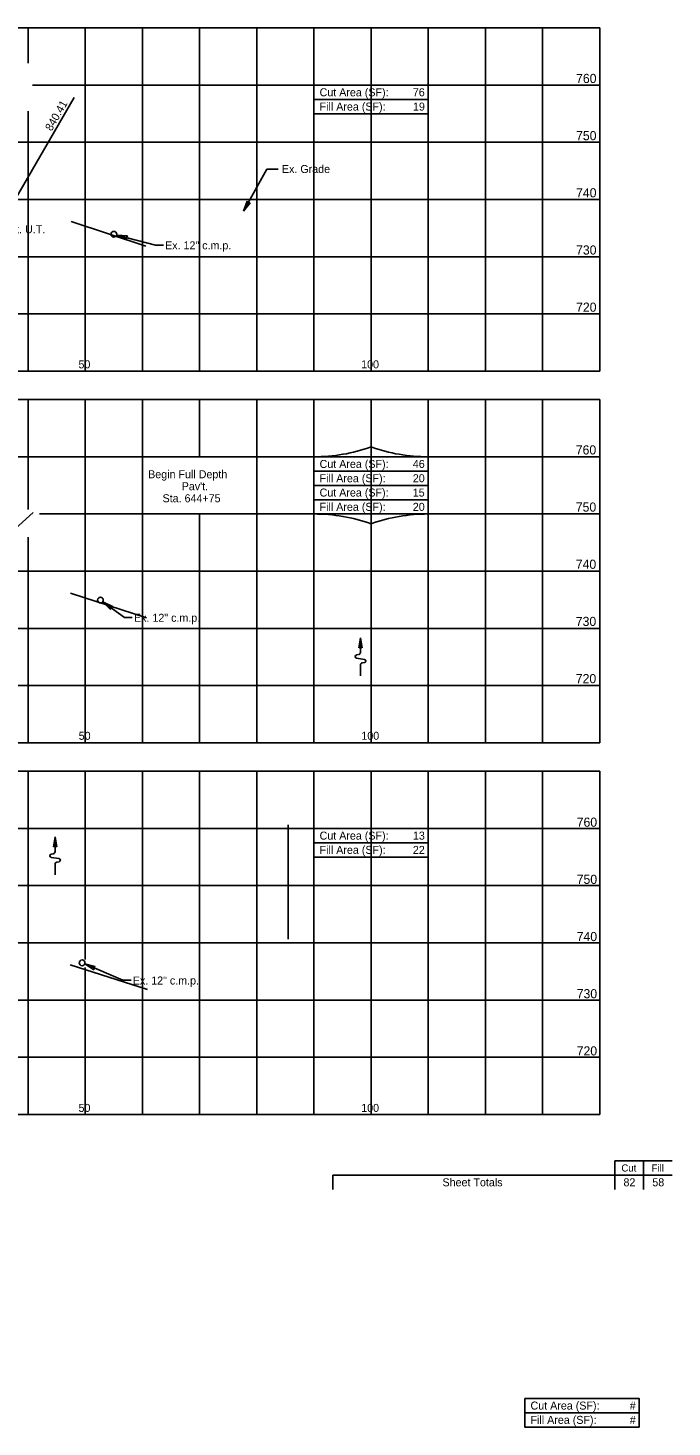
# Model space of a CAD drawing. Extents: x -475 to 76, y 0 to 417.
# Drawn here: x -455.81 to -444.54, y 392.1 to 416.57 of the extents above; entities that cross this region are included whole.
import ezdxf

# ---------------------------------------------------------------- set-up
doc = ezdxf.new("R2010")
doc.units = 0
for name, color, linetype in [('Default', 7, 'Continuous'), ('DR_X_Culvert', 7, 'Continuous'), ('DR_X_Storm_Sewer', 7, 'Continuous'), ('RW_X_Esmt_SH', 7, 'Continuous'), ('SC_Scratch1', 7, 'Continuous'), ('SC_Scratch10', 7, 'Continuous'), ('SH_Masking', 7, 'Continuous'), ('SV_P_Mon_Cells_Set', 7, 'Continuous')]:
    doc.layers.add(name, color=color, linetype=linetype)

msp = doc.modelspace()

# ---------------------------------------------------------------- linework, layer by layer
at = {"layer": 'Default'}
for p, q in [((-451.632, 414.099), (-452.039, 413.361)), ((-451.432, 414.099), (-451.632, 414.099)), ((-452.039, 413.361), (-451.977, 413.538)), ((-451.923, 413.508), (-452.039, 413.361)), ((-451.977, 413.538), (-451.977, 413.538)), ((-451.923, 413.508), (-451.923, 413.508)), ((-454.071, 412.929), (-454.257, 412.946)), ((-454.257, 412.946), (-454.086, 412.869)), ((-454.257, 412.946), (-453.577, 412.771)), ((-454.086, 412.869), (-454.086, 412.869)), ((-454.071, 412.929), (-454.071, 412.929)), ((-453.442, 412.771), (-453.577, 412.771)), ((-456.79, 407.122), (-455.721, 408.09)), ((-454.333, 406.448), (-454.501, 406.531)), ((-454.501, 406.531), (-454.369, 406.398)), ((-454.501, 406.531), (-454.12, 406.258)), ((-454.333, 406.448), (-454.333, 406.448)), ((-454.369, 406.398), (-454.369, 406.398)), ((-453.986, 406.258), (-454.12, 406.258)), ((-455.366, 402.245), (-455.337, 402.418)), ((-455.337, 402.418), (-455.308, 402.244)), ((-455.337, 402.162), (-455.337, 402.418)), ((-455.407, 402.117), (-455.367, 402.125)), ((-455.267, 402.041), (-455.406, 402.062)), ((-455.366, 402.245), (-455.366, 402.245)), ((-455.308, 402.244), (-455.308, 402.244)), ((-455.337, 401.756), (-455.337, 401.941)), ((-455.306, 401.978), (-455.266, 401.985)), ((-454.636, 400.153), (-454.818, 400.197)), ((-454.818, 400.197), (-454.66, 400.096)), ((-454.818, 400.197), (-454.151, 399.914)), ((-454.66, 400.096), (-454.66, 400.096)), ((-454.636, 400.153), (-454.636, 400.153)), ((-454.007, 399.914), (-454.151, 399.914)), ((-445.544, 396.254), (-445.544, 396.754)), ((-445.044, 396.254), (-445.044, 396.754)), ((-450.48, 396.254), (-450.48, 396.504))]:
    msp.add_line(p, q, dxfattribs=at)
for centre, radius, start, end in [((-451.927, 413.564), 0.0563, 207.3099, 273.9906), ((-454.033, 412.888), 0.0563, 132.5011, 199.1819), ((-454.313, 406.396), 0.0563, 111.2567, 177.9375), ((-455.337, 402.2), 0.0527, 56.178, 122.8588), ((-455.402, 402.09), 0.0281, 100.6197, 261.4692), ((-455.374, 402.162), 0.0375, 280.6197, 360), ((-455.272, 402.013), 0.0281, 280.6197, 81.4692), ((-455.299, 401.941), 0.0375, 100.6197, 180), ((-454.605, 400.106), 0.0563, 123.9422, 190.623)]:
    msp.add_arc(centre, radius, start, end, dxfattribs=at)
at = {"layer": 'DR_X_Culvert'}
for centre in [(-454.306, 412.959), (-454.542, 406.561), (-454.864, 400.217)]:
    msp.add_circle(centre, 0.05, dxfattribs=at)
at = {"layer": 'DR_X_Storm_Sewer'}
for p, q in [((-455.054, 413.183), (-453.746, 412.751)), ((-455.066, 406.683), (-453.735, 406.251)), ((-455.072, 400.183), (-453.719, 399.751))]:
    msp.add_line(p, q, dxfattribs=at)
at = {"layer": 'RW_X_Esmt_SH'}
msp.add_line((-451.256, 400.63), (-451.256, 402.63), dxfattribs=at)
at = {"layer": 'SC_Scratch1'}
for p, q in [((-450.809, 415.567), (-448.809, 415.567)), ((-450.809, 415.567), (-450.809, 415.067)), ((-448.809, 415.567), (-448.809, 415.067)), ((-450.809, 415.317), (-448.809, 415.317)), ((-450.809, 415.067), (-448.809, 415.067)), ((-450.809, 409.067), (-448.809, 409.067)), ((-450.809, 409.067), (-450.809, 408.567)), ((-448.809, 409.067), (-450.809, 409.067)), ((-448.809, 409.067), (-448.809, 408.567)), ((-450.809, 408.817), (-448.809, 408.817)), ((-450.809, 408.567), (-448.809, 408.567)), ((-450.809, 408.567), (-448.809, 408.567)), ((-450.809, 408.567), (-450.809, 408.067)), ((-448.809, 408.567), (-448.809, 408.067)), ((-450.809, 408.317), (-448.809, 408.317)), ((-450.809, 408.067), (-448.809, 408.067)), ((-448.809, 408.067), (-450.809, 408.067)), ((-450.024, 405.728), (-449.995, 405.901)), ((-450.024, 405.728), (-450.024, 405.728)), ((-449.995, 405.901), (-449.966, 405.727)), ((-449.995, 405.645), (-449.995, 405.901)), ((-449.966, 405.727), (-449.966, 405.728)), ((-450.065, 405.601), (-450.026, 405.608)), ((-449.925, 405.524), (-450.064, 405.545)), ((-449.964, 405.461), (-449.924, 405.469)), ((-449.995, 405.239), (-449.995, 405.424)), ((-450.809, 402.567), (-448.809, 402.567)), ((-450.809, 402.567), (-450.809, 402.067)), ((-448.809, 402.567), (-448.809, 402.067)), ((-450.809, 402.317), (-448.809, 402.317)), ((-450.809, 402.067), (-448.809, 402.067)), ((-445.544, 396.754), (-444.544, 396.754)), ((-450.48, 396.504), (-444.544, 396.504)), ((-447.119, 392.599), (-445.119, 392.599)), ((-447.119, 392.599), (-447.119, 392.099)), ((-445.119, 392.599), (-445.119, 392.099)), ((-447.119, 392.349), (-445.119, 392.349)), ((-447.119, 392.099), (-445.119, 392.099))]:
    msp.add_line(p, q, dxfattribs=at)
for centre, radius, start, end in [((-450.809, 412.067), 3, 270, 289.4712), ((-448.809, 412.067), 3, 250.5288, 270), ((-450.809, 405.067), 3, 70.5288, 90), ((-448.809, 405.067), 3, 90, 109.4712), ((-449.995, 405.684), 0.0527, 56.178, 122.8588), ((-450.06, 405.573), 0.0281, 100.6197, 261.4692), ((-450.032, 405.645), 0.0375, 280.6197, 360), ((-449.957, 405.424), 0.0375, 100.6197, 180), ((-449.93, 405.496), 0.0281, 280.6197, 81.4692)]:
    msp.add_arc(centre, radius, start, end, dxfattribs=at)
at = {"layer": 'SC_Scratch10'}
msp.add_line((-456.009, 413.608), (-455.004, 415.348), dxfattribs=at)
at = {"layer": 'SH_Masking'}
for points in [[(-450.809, 415.567), (-448.809, 415.567), (-448.809, 415.067), (-450.809, 415.067)], [(-450.809, 409.067), (-448.809, 409.067), (-448.809, 408.567), (-450.809, 408.567)], [(-450.809, 408.567), (-448.809, 408.567), (-448.809, 408.067), (-450.809, 408.067)], [(-450.809, 402.567), (-448.809, 402.567), (-448.809, 402.067), (-450.809, 402.067)], [(-447.119, 392.599), (-445.119, 392.599), (-445.119, 392.099), (-447.119, 392.099)]]:
    msp.add_lwpolyline(points, close=True, dxfattribs=at)
at = {"layer": 'SV_P_Mon_Cells_Set'}
for p, q in [((-473.809, 416.567), (-445.809, 416.567)), ((-455.809, 415.95), (-455.809, 416.567)), ((-454.809, 410.567), (-454.809, 416.567)), ((-453.809, 410.567), (-453.809, 416.567)), ((-452.809, 410.567), (-452.809, 416.567)), ((-451.809, 410.567), (-451.809, 416.567)), ((-450.809, 410.567), (-450.809, 416.567)), ((-449.809, 410.567), (-449.809, 416.567)), ((-448.809, 410.567), (-448.809, 416.567)), ((-447.809, 410.567), (-447.809, 416.567)), ((-446.809, 410.567), (-446.809, 416.567)), ((-445.809, 410.567), (-445.809, 416.567)), ((-455.733, 415.567), (-445.809, 415.567)), ((-455.809, 410.567), (-455.809, 415.11)), ((-473.809, 414.567), (-445.809, 414.567)), ((-461.544, 413.567), (-445.809, 413.567)), ((-473.809, 412.567), (-445.809, 412.567)), ((-465.495, 411.567), (-445.809, 411.567)), ((-473.809, 410.567), (-445.809, 410.567)), ((-473.809, 410.067), (-445.809, 410.067)), ((-455.809, 408.143), (-455.809, 410.067)), ((-454.809, 404.067), (-454.809, 410.067)), ((-453.809, 404.067), (-453.809, 410.067)), ((-452.809, 409.067), (-452.809, 410.067)), ((-451.809, 404.067), (-451.809, 410.067)), ((-450.809, 404.067), (-450.809, 410.067)), ((-449.809, 404.067), (-449.809, 410.067)), ((-448.809, 404.067), (-448.809, 410.067)), ((-447.809, 404.067), (-447.809, 410.067)), ((-446.809, 404.067), (-446.809, 410.067)), ((-445.809, 404.067), (-445.809, 410.067)), ((-473.809, 409.067), (-445.809, 409.067)), ((-455.606, 408.067), (-445.809, 408.067)), ((-452.809, 404.067), (-452.809, 408.067)), ((-455.809, 404.067), (-455.809, 407.66)), ((-462.646, 407.067), (-445.809, 407.067)), ((-463.142, 406.067), (-445.809, 406.067)), ((-473.809, 405.067), (-445.809, 405.067)), ((-473.809, 404.067), (-445.809, 404.067)), ((-473.809, 403.567), (-445.809, 403.567)), ((-455.809, 397.567), (-455.809, 403.567)), ((-454.809, 400.278), (-454.809, 403.567)), ((-453.809, 397.567), (-453.809, 403.567)), ((-452.809, 397.567), (-452.809, 403.567)), ((-451.809, 397.567), (-451.809, 403.567)), ((-450.809, 397.567), (-450.809, 403.567)), ((-449.809, 397.567), (-449.809, 403.567)), ((-448.809, 397.567), (-448.809, 403.567)), ((-447.809, 397.567), (-447.809, 403.567)), ((-446.809, 397.567), (-446.809, 403.567)), ((-445.809, 397.567), (-445.809, 403.567)), ((-473.809, 402.567), (-445.809, 402.567)), ((-473.809, 401.567), (-445.809, 401.567)), ((-456.377, 400.567), (-445.809, 400.567)), ((-454.809, 397.567), (-454.809, 400.134)), ((-463.047, 399.567), (-445.809, 399.567)), ((-473.809, 398.567), (-445.809, 398.567)), ((-473.809, 397.567), (-445.809, 397.567))]:
    msp.add_line(p, q, dxfattribs=at)

# ---------------------------------------------------------------- texts
at = {"layer": 'Default'}
for s, height, p in [('Ex. Grade', 0.14, (-451.368, 414.03)), ('Ex. U.T.', 0.14, (-456.184, 412.977)), ('Ex. 12" c.m.p.', 0.14, (-453.412, 412.695)), ('Ex. 12" c.m.p.', 0.14, (-453.956, 406.182)), ('Ex. 12" c.m.p.', 0.14, (-453.977, 399.838)), ('Cut', 0.125, (-445.429, 396.567)), ('Fill', 0.125, (-444.899, 396.567)), ('Sheet Totals', 0.14, (-448.559, 396.309)), ('82', 0.14, (-445.393, 396.309)), ('58', 0.14, (-444.888, 396.309))]:
    msp.add_text(s, height=height, dxfattribs=at).set_placement(p)
at = {"layer": 'SC_Scratch10'}
for s, height, p in [('760', 0.16, (-446.222, 415.604)), ('Cut Area (SF):', 0.14, (-450.709, 415.372)), ('76', 0.14, (-449.078, 415.372)), ('Fill Area (SF):', 0.14, (-450.709, 415.122)), ('19', 0.14, (-449.075, 415.122)), ('750', 0.16, (-446.222, 414.604)), ('740', 0.16, (-446.222, 413.604)), ('730', 0.16, (-446.222, 412.604)), ('720', 0.16, (-446.222, 411.604)), ('50', 0.14, (-454.927, 410.614)), ('100', 0.14, (-449.982, 410.614)), ('760', 0.16, (-446.227, 409.108)), ('Cut Area (SF):', 0.14, (-450.709, 408.872)), ('46', 0.14, (-449.078, 408.872)), ('Begin Full Depth', 0.14, (-453.708, 408.692)), ("Pav't.", 0.14, (-453.121, 408.482)), ('Fill Area (SF):', 0.14, (-450.709, 408.622)), ('20', 0.14, (-449.078, 408.622)), ('Sta. 644+75', 0.14, (-453.456, 408.272)), ('Cut Area (SF):', 0.14, (-450.709, 408.372)), ('15', 0.14, (-449.079, 408.372)), ('Fill Area (SF):', 0.14, (-450.709, 408.122)), ('20', 0.14, (-449.078, 408.122)), ('750', 0.16, (-446.227, 408.108)), ('740', 0.16, (-446.227, 407.108)), ('730', 0.16, (-446.227, 406.108)), ('720', 0.16, (-446.227, 405.108)), ('50', 0.14, (-454.923, 404.118)), ('100', 0.14, (-449.978, 404.118)), ('760', 0.16, (-446.211, 402.597)), ('Cut Area (SF):', 0.14, (-450.709, 402.372)), ('13', 0.14, (-449.076, 402.372)), ('Fill Area (SF):', 0.14, (-450.709, 402.122)), ('22', 0.14, (-449.077, 402.122)), ('750', 0.16, (-446.211, 401.597)), ('740', 0.16, (-446.211, 400.597)), ('730', 0.16, (-446.211, 399.597)), ('720', 0.16, (-446.211, 398.597)), ('50', 0.14, (-454.926, 397.61)), ('100', 0.14, (-449.981, 397.61)), ('Cut Area (SF):', 0.14, (-447.019, 392.404)), ('#', 0.14, (-445.282, 392.404)), ('Fill Area (SF):', 0.14, (-447.019, 392.154)), ('#', 0.14, (-445.282, 392.154))]:
    msp.add_text(s, height=height, dxfattribs=at).set_placement(p)
msp.add_text('840.41', height=0.14, rotation=60, dxfattribs=at).set_placement((-455.398, 414.753))

doc.saveas('drawing.dxf')
